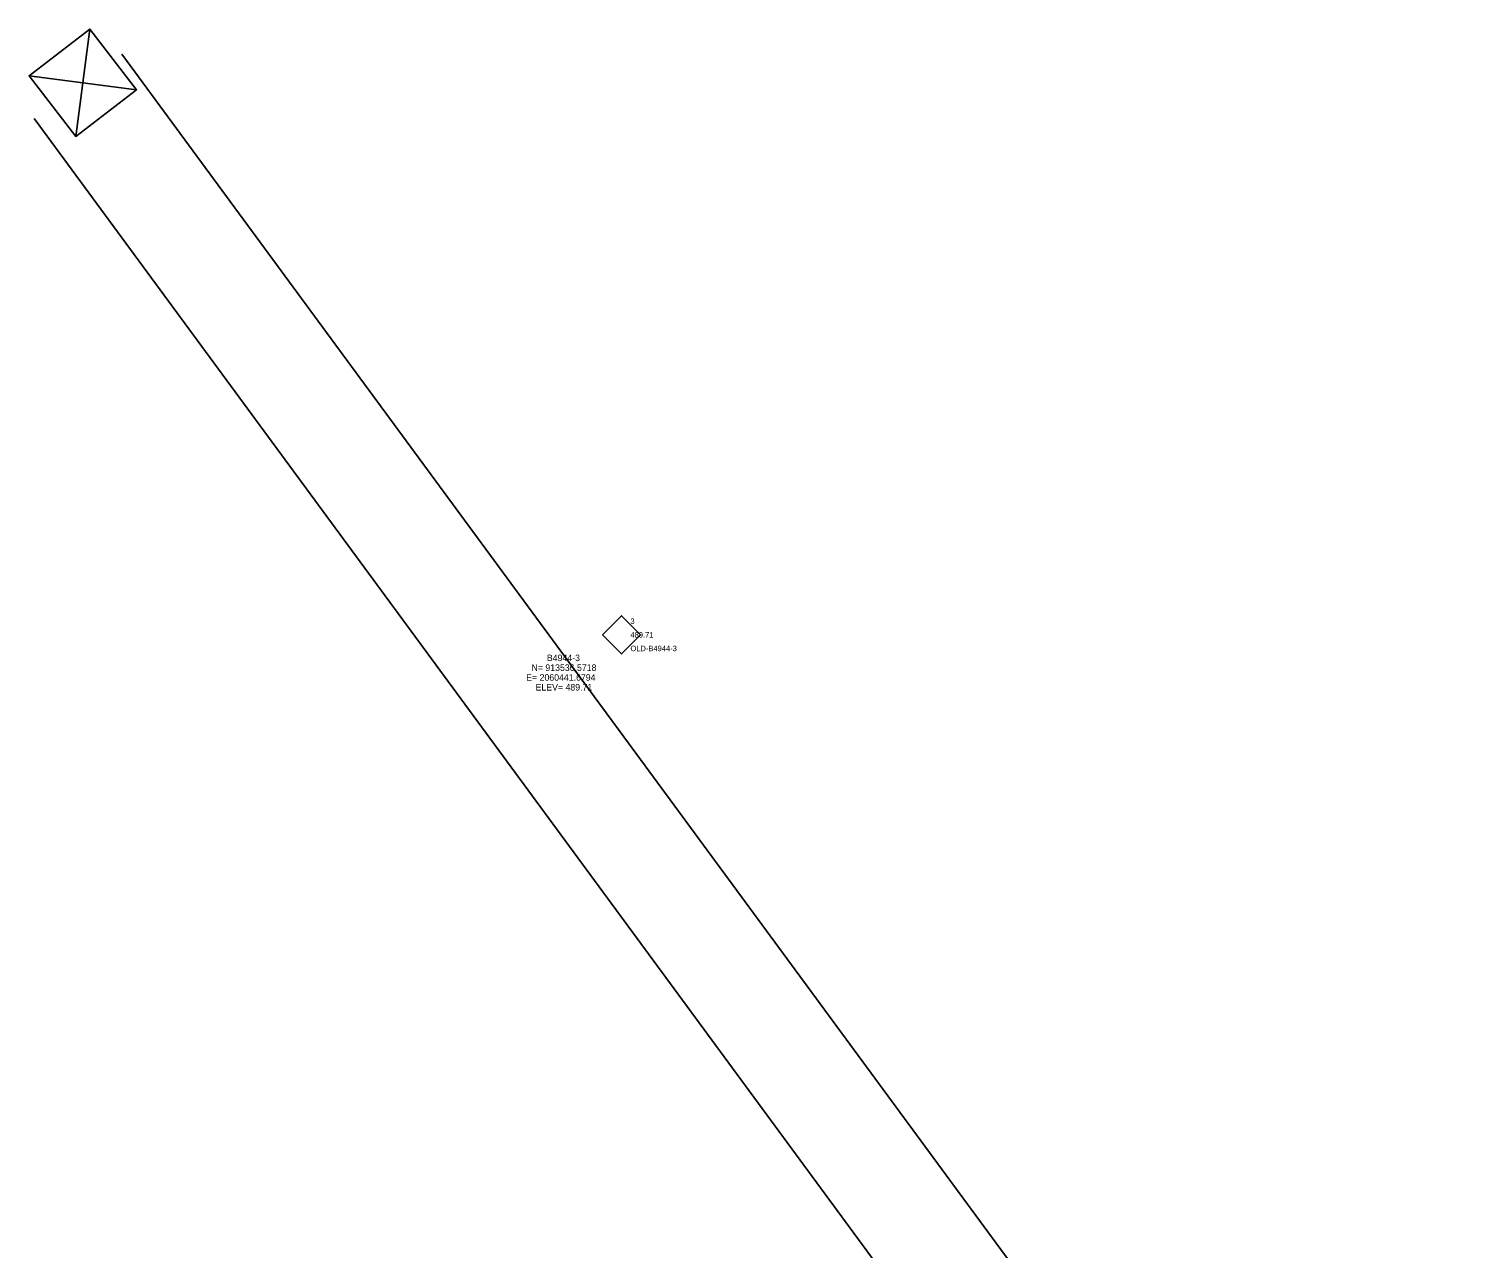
# Model space of a CAD drawing. Extents: x 2060057 to 2062431, y 911685 to 913703.
# Drawn here: x 2060278.7 to 2060678.8, y 913367.6 to 913703.3 of the extents above; entities that cross this region are included whole.
import ezdxf

# ---------------------------------------------------------------- set-up
doc = ezdxf.new("R2010")
doc.units = 0
for name, color, linetype in [('CTL Supplemental Horizontal and Vertical CELL', 7, 'Continuous'), ('CTL Supplemental Horizontal and Vertical Cogo Comment', 7, 'Continuous'), ('CTL Supplemental Horizontal and Vertical Cogo Elevation', 7, 'Continuous'), ('CTL Supplemental Horizontal and Vertical Cogo Number', 7, 'Continuous'), ('CTL Supplemental Horizontal and Vertical Text', 7, 'Continuous'), ('Exist Utilities Power Tower CELL', 7, 'Continuous'), ('Exist Utilities Power UG Cable', 7, 'Continuous')]:
    doc.layers.add(name, color=color, linetype=linetype)

msp = doc.modelspace()

# ---------------------------------------------------------------- linework, layer by layer
at = {"layer": 'CTL Supplemental Horizontal and Vertical CELL'}
msp.add_line((2060441.68, 913536.57), (2060441.68, 913536.57), dxfattribs=at)
msp.add_lwpolyline([(2060436.46, 913536.59), (2060441.71, 913541.83), (2060446.96, 913536.58), (2060441.71, 913531.34)], close=True, dxfattribs=at)
at = {"layer": 'Exist Utilities Power Tower CELL'}
msp.add_lwpolyline([(2060291.53, 913673.73), (2060308.24, 913686.57), (2060295.39, 913703.28), (2060278.69, 913690.44), (2060291.53, 913673.73), (2060295.39, 913703.28), (2060278.69, 913690.44), (2060308.24, 913686.57)], dxfattribs=at)
at = {"layer": 'Exist Utilities Power UG Cable'}
for points in [[(2060304.19, 913696.4), (2061127.5, 912576.77)], [(2060280.08, 913678.67), (2061103.4, 912559.04)]]:
    msp.add_lwpolyline(points, dxfattribs=at)

# ---------------------------------------------------------------- texts
at = {"layer": 'CTL Supplemental Horizontal and Vertical Cogo Comment'}
msp.add_text('OLD-B4944-3', height=1.5, dxfattribs=at).set_placement((2060444.18, 913532.07))
at = {"layer": 'CTL Supplemental Horizontal and Vertical Cogo Elevation'}
msp.add_text('489.71', height=1.5, dxfattribs=at).set_placement((2060444.18, 913535.82))
at = {"layer": 'CTL Supplemental Horizontal and Vertical Cogo Number'}
msp.add_text('3', height=1.5, dxfattribs=at).set_placement((2060444.18, 913539.57))
at = {"layer": 'CTL Supplemental Horizontal and Vertical Text'}
for s, p in [('B4944-3', (2060421.19, 913529.34)), ('E= 2060441.6794', (2060415.5, 913523.94)), ('N= 913536.5718', (2060416.96, 913526.64)), ('ELEV= 489.71', (2060418.08, 913521.24))]:
    msp.add_text(s, height=1.8, rotation=0, dxfattribs=at).set_placement(p)

doc.saveas('drawing.dxf')
